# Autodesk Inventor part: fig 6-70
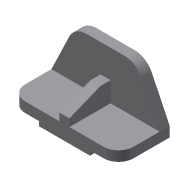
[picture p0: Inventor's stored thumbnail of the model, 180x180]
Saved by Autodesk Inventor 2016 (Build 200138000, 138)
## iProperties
Shininess: 77.0
Length Units: 11269
Angle Units: 11279
Time Units: 11290
Mass Units: 11283
Length Display Precision: 3
Angle Display Precision: 2
Created: 2001-12
Part Number: fig 6-70
Document SubType Name: Modeling
Designer: Renu Muthoo
Density: 1 g/cm^3
Material: Generic
Appearance: Default
Density: 0.0
Volumn: 0.0
Area: 0.0
PropertySet Name: Model Information
Control State: 0
Master: False
Checked Out: False
Author: Renu Muthoo
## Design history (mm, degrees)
sketch "Sketch2"
  geometry: L1 (-67.219, 19.116)-(148.781, 19.116); L2 (148.781, 19.116)-(148.781, -0.884); L3 (-67.219, -0.884)-(-67.219, 19.116); L4 (-10.219, -0.884)-(-10.219, -9.884); L5 (-10.219, -9.884)-(91.781, -9.884); L6 (91.781, -9.884)-(91.781, -0.884); L7 (148.781, -0.884)-(91.781, -0.884); L8 (-10.219, -0.884)-(-67.219, -0.884)
  constraints: 16 end point, 5 parallel, 4 perpendicular, 2 equal length, 1 horizontal
  dimensions: "d0" = 102 distance of L4.end L5.end; "d1" = 57 distance of L4.start L3.start; "d2" = 29 distance between parallel lines of L1 L5; "d3" = 20 distance of L1.end L2.end
extrude "Extrusion1" new body sketch "Sketch2" distance "d4" = 102; taper "d5" = 0 deg
sketch "Sketch3"
  geometry: L1 (67.219, -19.116)-(-148.781, -19.116) reference; L2 (67.219, -19.116)-(31.475, -93.564); L3 (-2.781, -115.116)-(-78.781, -115.116); L4 (-113.038, -93.564)-(-148.781, -19.116); A1 r 38 centre (-2.781, -77.116) between (-2.781, -115.116) and (31.475, -93.564); A2 r 38 centre (-78.781, -77.116) between (-113.038, -93.564) and (-78.781, -115.116)
  constraints: 6 end point, 4 point on circle, 4 tangent, 2 centre point, 1 equal length, 1 equal radius, 1 parallel
  dimensions: "d6" = 96 distance between parallel lines of L3 L1; "d7" = 38 radius of A1; "d8" = 76 distance of A2.centre A1.centre
extrude "Extrusion2" join sketch "Sketch3" distance "d9" = 20; taper "d10" = 0 deg
fillet "Fillet1" dims "d11" = 30
workplane "Work Plane1"
sketch "Sketch7"
  geometry: L1 (0, -82)-(-15, -82); L2 (-15, -82)-(-40, -20); L3 (-40, -20)-(-40, 0); L4 (0, -82)-(20, -82) reference; L5 (0, 0)-(-74.447, 0) reference
  constraints: 6 end point, 2 point on line, 1 horizontal, 1 perpendicular
  dimensions: "d32" = 20 distance of L2.end L3.end; "d33" = 15 distance of L1.start L1.end; "d34" = 40 distance of L5.start L3.end
feature "Rib4" sketch "Sketch7" dims "d55" = 1, "d56" = 20, "d57" = 0
body "Solid1"
other parameters: "d12" = -108
